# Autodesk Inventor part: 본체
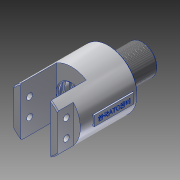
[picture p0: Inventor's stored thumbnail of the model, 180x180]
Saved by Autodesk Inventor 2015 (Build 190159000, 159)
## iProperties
Created: 2019-02
Part Number: 본체
Material: 알루미늄 6061
Document SubType Name: Modeling
Designer: now
Density: 2.7 g/cm^3
Appearance: 알루미늄 - 평지
Mass: 346.054 g
Surface Area: 290.4 cm^2
Volume: 128.168 cm^3
Author: now
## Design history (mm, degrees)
sketch "스케치1"
  geometry: C1 r 29 at (0, 0); 1 further point
  constraints: 1 centre point, 1 coincident
  dimensions: "d0" = 58 diameter of C1
extrude "돌출1" new body sketch "스케치1" distance "d1" = 74; taper "d2" = 0 deg
sketch "스케치2"
  geometry: C1 r 29 at (0, 0) reference; C2 r 13 at (0, 0)
  constraints: 1 centre point, 1 coincident
  dimensions: "d3" = 26 diameter of C2
extrude "돌출2" join sketch "스케치2" distance "d4" = 5; taper "d5" = 0 deg
sketch "스케치3"
  geometry: C1 r 13 at (0, 0) reference; C2 r 15 at (0, 0)
  constraints: 1 centre point, 1 coincident
  dimensions: "d6" = 30 diameter of C2
extrude "돌출3" join sketch "스케치3" distance "d7" = 29; taper "d8" = 0 deg
sketch "스케치4"
  geometry: L1 (-29, 0)-(-29, 74) reference; L2 (-29, 74)-(-13, 74) reference; L3 (-13, 74)-(-13, 79) reference; L4 (-13, 79)-(-15, 79) reference; L5 (-15, 79)-(-15, 108) reference; L6 (-15, 108)-(15, 108) reference; L7 (15, 108)-(15, 79) reference; L8 (15, 79)-(13, 79) reference; L9 (13, 79)-(13, 74) reference; L10 (13, 74)-(29, 74) reference; L11 (29, 74)-(29, 0) reference; L12 (29, 0)-(-29, 0) reference; L13 (15, 36)-(-15, 36); L14 (-15, 36)-(-15, 0); L15 (-15, 0)-(15, 0); L16 (15, 0)-(15, 36); L17 (15, 36)-(-15, 0); L18 (-15, 36)-(15, 0); 4 further points
  constraints: 12 end point, 4 midpoint, 2 parallel, 1 horizontal, 1 perpendicular, 1 point on line, 1 vertical alignment
  dimensions: "d9" = 36 distance of L15.end L13.start; "d10" = 30 distance of L13.start L13.end
extrude "돌출4" cut sketch "스케치4" stored distance "d11" = 29; taper "d12" = 0 deg
sketch "스케치5"
  geometry: L1 (-13, 79)-(-15, 79) reference; L2 (-15, 79)-(-15, 108) reference; L3 (-15, 108)-(15, 108) reference; L4 (15, 108)-(15, 79) reference; L5 (15, 79)-(13, 79) reference; L6 (13, 79)-(13, 74) reference; L7 (13, 74)-(29, 74) reference; L8 (29, 74)-(29, 0) reference; L9 (29, 0)-(15, 0) reference; L10 (15, 0)-(15, 36) reference; L11 (15, 36)-(-15, 36) reference; L12 (-15, 36)-(-15, 0) reference; L13 (-15, 0)-(-29, 0) reference; L14 (-29, 0)-(-29, 74) reference; L15 (-29, 74)-(-13, 74) reference; L16 (-13, 74)-(-13, 79) reference; L17 (-29, 16)-(-22, 16); L18 (-22, 16)-(-22, 0); L19 (-22, 0)-(-29, 0); L20 (-29, 0)-(-29, 16); 1 further point
  constraints: 8 end point, 2 parallel, 1 horizontal, 1 perpendicular
  dimensions: "d14" = 22 distance from line of point (0, 0) L18; "d15" = 16 distance of L17.end L18.end
extrude "돌출5" cut sketch "스케치5" stored distance "d16" = 29; taper "d17" = 0 deg
sketch "스케치6"
  geometry: L1 (0, 0)-(-37.789, 0) reference; 2 further points
  dimensions: "d18" = 9 distance from line of L1 point (-27.894, 9); "d19" = 9 horizontal distance of point (-18.894, 0) point (-27.894, 9)
hole "구멍1" sketch "스케치6" at (-27.894, 9) diameter "d20" = 6; stored, may be unused: countersink angle "d24" = 90 deg, drill point angle "d26" = 118 deg; dims "d21" = 6, "d22" = 4, "d23" = 2, "d25" = 8
sketch "스케치8"
  geometry: L1 (79, 13)-(79, 15) reference; L2 (79, 15)-(108, 15) reference; L3 (108, 15)-(108, -15) reference; L4 (108, -15)-(79, -15) reference; L5 (79, -15)-(79, -13) reference; L6 (79, -13)-(74, -13) reference; L7 (74, -13)-(74, -29) reference; L8 (74, -29)-(36, -29) reference; L9 (36, -29)-(36, 29) reference; L10 (36, 29)-(74, 29) reference; L11 (74, 29)-(74, 13) reference; L12 (74, 13)-(79, 13) reference; L13 (36, 0)-(63, 0); L14 (63, 0)-(63, 16); L15 (63, 16)-(56, 16); L16 (56, 16)-(56, 14); L17 (56, 14)-(52.35, 14); L18 (47.65, 14)-(47.65, 17); L19 (47.65, 17)-(52.35, 17); L20 (52.35, 17)-(52.35, 14); L21 (38.65, 14)-(38.65, 17); L22 (38.65, 17)-(43.35, 17); L23 (43.35, 17)-(43.35, 14); L24 (36, 14)-(36, 0); L25 (36, -24.819)-(36, 24.819) reference; L26 (41, 21)-(41, -0.922); L27 (50, 20.712)-(50, -2.282); L28 (38.65, 14)-(36, 14); L29 (47.65, 14)-(43.35, 14); 3 further points
  constraints: 32 end point, 9 perpendicular, 6 point on line, 3 midpoint, 3 vertical, 1 collinear
  dimensions: "d36" = 5 distance between parallel lines of L9 L26; "d37" = 9 distance between parallel lines of L27 L26; "d38" = 4.7 distance between parallel lines of L23 L21; "d39" = 4.7 distance between parallel lines of L20 L18; "d40" = 17 distance between parallel lines of L13 L22; "d42" = 7 distance of L14.end L15.end; "d43" = 27 distance between parallel lines of L24 L14; "d44" = 16 distance of L13.end L14.end; "d45" = 14 distance between parallel lines of L13 L28; "d46" = 14 distance between parallel lines of L13 L29
revolve "회전1" sketch "스케치8" stored, may be unused: angle "d47" = 90 deg
feature "스레드1" dims "d48" = 10, "d49" = 0
sketch "스케치9"
  geometry: C1 r 15 at (0, 0) reference
hole "구멍2" sketch "스케치9" at (0, 0) diameter "d50" = 12.376; stored, may be unused: countersink angle "d54" = 90 deg, drill point angle "d56" = 0 deg; dims "d51" = 18, "d52" = 28, "d53" = 2, "d55" = 22
sketch "스케치10"
  geometry: C1 r 6.188 at (0, 0) reference
hole "구멍3" sketch "스케치10" at (0, 0) diameter "d57" = 8; stored, may be unused: countersink angle "d61" = 90 deg, drill point angle "d63" = 0 deg; dims "d58" = 18, "d59" = 28, "d60" = 2, "d62" = 22
node "작업 평면1"
sketch "스케치11"
  geometry: L1 (29, 5)-(69, 5); L2 (69, 5)-(69, -5); L3 (69, -5)-(29, -5); L4 (29, -5)-(29, 5); L5 (74, -29)-(74, 29) reference; 2 further points
  constraints: 8 end point, 2 parallel, 1 horizontal, 1 horizontal alignment, 1 midpoint, 1 perpendicular
  dimensions: "d65" = 10 distance of L3.end L1.start; "d66" = 40 distance of L1.start L1.end; "d67" = 5 distance between parallel lines of L5 L2
extrude "돌출6" join sketch "스케치11" stored distance "d68" = 29; taper "d69" = 0 deg
sketch "스케치12"
  geometry: L1 (-5, 29)-(-5, 69) reference; L2 (5, 29)-(-5, 29) reference; 5 further points
  constraints: 3 midpoint, 1 vertical alignment, 1 other
  dimensions: "d82" = 20 distance from line of point (0, 49) L2
feature "엠보싱1" sketch "스케치12" dims "d70" = 0.5, "d71" = 0
fillet "모깎기1" dims "d72" = 0.8
chamfer "모따기1" distance "d73" = 1; stored, may be unused: second distance "d74" = 2, angle "d75" = 45 deg
chamfer "모따기2" distance "d76" = 1; stored, may be unused: second distance "d77" = 2, angle "d78" = 45 deg
chamfer "모따기3" distance "d79" = 1; stored, may be unused: second distance "d80" = 2, angle "d81" = 45 deg
node "솔리드1"
mirror "대칭1"
mirror "대칭2"
node "절단 모서리 투영1"
node "절단 모서리 투영2"
node "절단 모서리 투영4"
other parameters: "d41" = 14
